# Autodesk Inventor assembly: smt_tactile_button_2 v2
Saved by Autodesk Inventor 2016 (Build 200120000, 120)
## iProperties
Created: 2016-09
Part Number: smt_tactile_button_2 v2
Document SubType Name: Assembly
Designer: Administrator
Author: Administrator
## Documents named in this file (5)
- c:\worker\convert-fusion-aug-2016\tmp\job-1\13\output\files\2055b865-881d-4af8-ae30-e7b46ec3c804\smt_tactile_button_2 v2.iam
- c:\worker\convert-fusion-aug-2016\tmp\job-1\13\output\files\2055b865-881d-4af8-ae30-e7b46ec3c804\Component43.ipt
- c:\worker\convert-fusion-aug-2016\tmp\job-1\13\output\files\2055b865-881d-4af8-ae30-e7b46ec3c804\Component44.ipt
- c:\worker\convert-fusion-aug-2016\tmp\job-1\13\output\files\2055b865-881d-4af8-ae30-e7b46ec3c804\Component45.ipt
- c:\worker\convert-fusion-aug-2016\tmp\job-1\13\output\files\2055b865-881d-4af8-ae30-e7b46ec3c804\Component46.ipt
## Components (4 placed, 4 different names)
1. Component43:1
2. Component44:1
3. Component45:1
4. Component46:1
